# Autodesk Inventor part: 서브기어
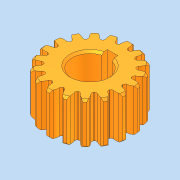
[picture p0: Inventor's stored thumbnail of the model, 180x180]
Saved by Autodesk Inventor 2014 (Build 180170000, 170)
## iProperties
Company: 한국ATC센터
Created: 2014-12
Part Number: 서브기어
Document SubType Name: Modeling
Designer: KYOUNG IL JANG
Density: 1 g/cm^3
Mass: 15.166 g
Surface Area: 69.6172 cm^2
Volume: 15.166 cm^3
Material: 일반
Appearance: 금속 1800F 열
Author: KYOUNG IL JANG
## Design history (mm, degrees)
sketch "스케치1"
  geometry: C1 r 15.5 at (0, 0); A1 r 1.155 centre (-2.906, 16.386) between (-2.542, 15.29) and (-1.751, 16.378); A2 r 5.602 centre (3.849, 16.522) between (-1.326, 18.666) and (-1.751, 16.378); A3 r 9.354 centre (7.378, 15.24) between (-0.682, 19.988) and (-1.326, 18.666); A4 r 1.155 centre (2.906, 16.386) between (1.751, 16.378) and (2.542, 15.29); A5 r 5.602 centre (-3.849, 16.522) between (1.751, 16.378) and (1.326, 18.666); A6 r 9.354 centre (-7.378, 15.24) between (1.326, 18.666) and (0.682, 19.988); A7 r 20 centre (0, 0) between (0.682, 19.988) and (-0.682, 19.988); A8 r 15.5 centre (0, 0) between (2.542, 15.29) and (-2.542, 15.29); 1 further point
  constraints: 16 point on circle, 9 centre point, 2 coincident
extrude "돌출1" new body sketch "스케치1" stored distance "d0" = 20; taper "d1" = 0 deg
extrude "돌출2" join sketch "스케치1" stored distance "d2" = 20; taper "d3" = 0 deg
chamfer "모따기1" distance "d4" = 1; stored, may be unused: second distance "d5" = 2, angle "d6" = 45 deg
hole "구멍1" diameter "d12" = 17; stored, may be unused: countersink angle "d16" = 90 deg, drill point angle "d18" = 118 deg; dims "d10" = 10, "d11" = 10, "d13" = 6, "d14" = 4, "d15" = 2, "d17" = 8
sketch "스케치2"
  geometry: L1 (-2.5, 8.124)-(-2.5, 10.8); L2 (-2.5, 10.8)-(2.5, 10.8); L3 (2.5, 10.8)-(2.5, 8.124); A1 r 8.5 centre (0, 0) between (-2.5, 8.124) and (2.5, 8.124) reference; 1 further point
  constraints: 6 end point, 2 parallel, 2 point on circle, 1 horizontal, 1 vertical
  dimensions: "d22" = 5 distance of L1.end L2.end; "d23" = 2.3 distance edge to line of A1 L2
extrude "돌출3" cut sketch "스케치2" stored distance "d24" = 20; taper "d25" = 0 deg
chamfer "모따기2" distance "d19" = 1; stored, may be unused: second distance "d20" = 2, angle "d21" = 45 deg
node "솔리드1"
pattern_circular "원형 패턴1" dims angle "d8" = 360 deg
